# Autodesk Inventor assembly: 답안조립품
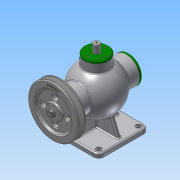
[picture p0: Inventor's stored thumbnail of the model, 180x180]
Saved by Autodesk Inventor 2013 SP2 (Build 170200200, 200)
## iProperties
Created: 2018-06
Part Number: 답안조립품
Document SubType Name: Assembly
Designer: Administrator
Author: Administrator
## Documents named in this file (19)
- C:\Users\Administrator\Desktop\480612V1013\답안조립품.iam
- C:\Users\Administrator\Desktop\480612V1013\본체.ipt
- C:\Users\Administrator\Desktop\480612V1013\V-벨트풀리.ipt
- C:\Users\Administrator\Desktop\480612V1013\너트 M8.ipt
- C:\Users\Administrator\Desktop\480612V1013\뒤커버.ipt
- C:\Users\Administrator\Desktop\480612V1013\멈춤링 15x1.ipt
- C:\Users\Administrator\Desktop\480612V1013\멈춤링 35x1.6.ipt
- 멈춤링 35x1.6.ipt
- C:\Users\Administrator\Desktop\480612V1013\베어링 6202.ipt
- 베어링 6202.ipt
- C:\Users\Administrator\Desktop\480612V1013\볼트 M4x12.ipt
- C:\Users\Administrator\Desktop\480612V1013\볼트 M4x16.ipt
- C:\Users\Administrator\Desktop\480612V1013\부시.ipt
- C:\Users\Administrator\Desktop\480612V1013\상부커버.ipt
- C:\Users\Administrator\Desktop\480612V1013\슬라이드.ipt
- C:\Users\Administrator\Desktop\480612V1013\앞커버.ipt
- C:\Users\Administrator\Desktop\480612V1013\오일 실 15 30 7.ipt
- C:\Users\Administrator\Desktop\480612V1013\키 4x4x12.ipt
- C:\Users\Administrator\Desktop\480612V1013\편심축.ipt
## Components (1 placed, 1 different names)
1. V-벨트풀리:1 — 플러쉬:1
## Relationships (1: Flush 1)
- 플러쉬:1 [Flush]: V-벨트풀리:1
